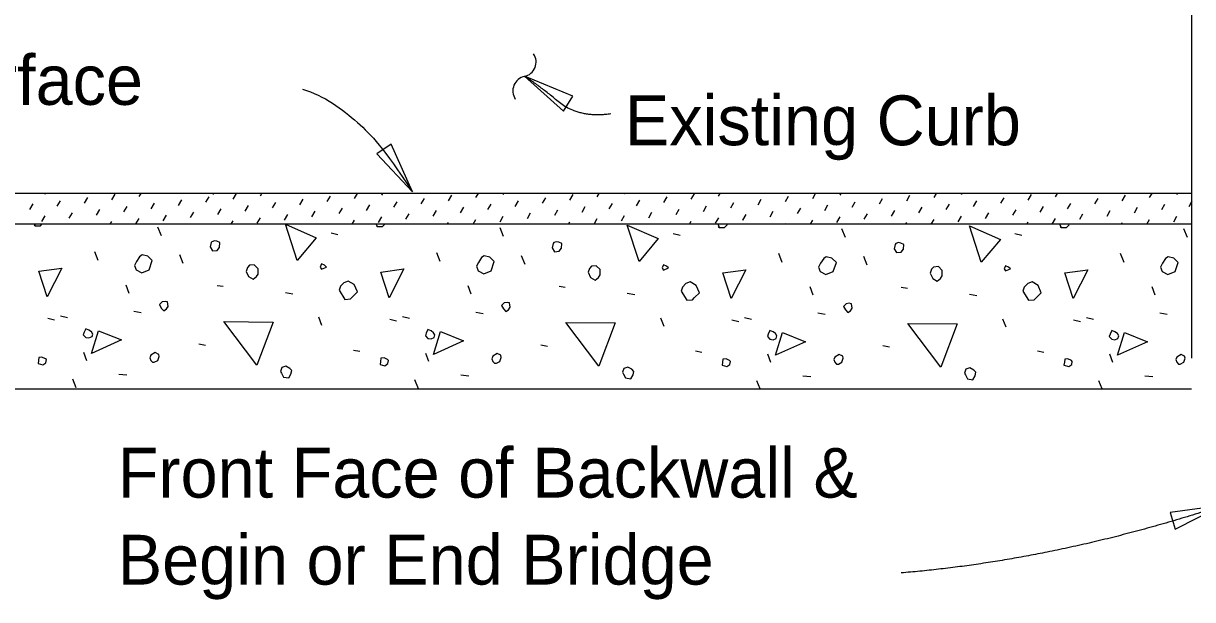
# Model space of a CAD drawing. Extents: x 21526.6 to 21598.7, y 56118.9 to 56155.9.
# Drawn here: x 21530.88 to 21535.614, y 56132.816 to 56135.148 of the extents above; entities that cross this region are included whole.
import ezdxf

# ---------------------------------------------------------------- set-up
doc = ezdxf.new("R2010")
doc.units = 0
for name, color, linetype in [('AdhocPoint_dp', 7, 'Continuous'), ('Border', 7, 'Continuous'), ('Patterning', 7, 'Continuous'), ('PlotBorder_dp', 7, 'Continuous')]:
    doc.layers.add(name, color=color, linetype=linetype)

msp = doc.modelspace()

# ---------------------------------------------------------------- linework, layer by layer
at = {"layer": 'AdhocPoint_dp'}
for p, q in [((21535.6096, 56135.2099), (21535.6096, 56133.7934)), ((21535.6096, 56134.46), (21527.2426, 56134.46)), ((21535.6096, 56134.335), (21527.2426, 56134.335)), ((21527.2426, 56133.6684), (21535.6096, 56133.6684))]:
    msp.add_line(p, q, dxfattribs=at)
at = {"layer": 'Patterning'}
for p, q in [((21530.9679, 56134.4567), (21530.9698, 56134.46)), ((21531.0168, 56134.4079), (21531.0297, 56134.4303)), ((21531.1274, 56134.4209), (21531.1404, 56134.4433)), ((21531.238, 56134.4338), (21531.251, 56134.4562)), ((21531.3487, 56134.4468), (21531.3563, 56134.46)), ((21531.4593, 56134.4598), (21531.4595, 56134.46)), ((21531.5081, 56134.4109), (21531.5211, 56134.4333)), ((21531.6188, 56134.4239), (21531.6317, 56134.4463)), ((21531.6499, 56134.4561), (21531.6501, 56134.4564)), ((21531.7294, 56134.4369), (21531.7424, 56134.4592)), ((21531.84, 56134.4498), (21531.846, 56134.46)), ((21531.9995, 56134.4139), (21532.0125, 56134.4363)), ((21532.1101, 56134.4269), (21532.1231, 56134.4493)), ((21532.2208, 56134.4399), (21532.2324, 56134.46)), ((21532.3314, 56134.4528), (21532.3356, 56134.46)), ((21532.4909, 56134.417), (21532.5038, 56134.4394)), ((21532.6015, 56134.4299), (21532.6145, 56134.4523)), ((21532.7121, 56134.4429), (21532.7221, 56134.46)), ((21532.8228, 56134.4559), (21532.8252, 56134.46)), ((21532.9822, 56134.42), (21532.9952, 56134.4424)), ((21533.0929, 56134.433), (21533.1058, 56134.4553)), ((21533.2035, 56134.4459), (21533.2117, 56134.46)), ((21533.3141, 56134.4589), (21533.3148, 56134.46)), ((21533.363, 56134.41), (21533.3759, 56134.4324)), ((21533.4736, 56134.423), (21533.4866, 56134.4454)), ((21533.5842, 56134.436), (21533.5972, 56134.4584)), ((21533.6949, 56134.4489), (21533.7013, 56134.46)), ((21533.8545, 56134.4139), (21533.8675, 56134.4363)), ((21533.9652, 56134.4269), (21533.9781, 56134.4493)), ((21534.0758, 56134.4399), (21534.0875, 56134.46)), ((21534.1864, 56134.4528), (21534.1906, 56134.46)), ((21534.3459, 56134.417), (21534.3589, 56134.4394)), ((21534.4565, 56134.4299), (21534.4695, 56134.4523)), ((21534.5672, 56134.4429), (21534.5771, 56134.46)), ((21534.6778, 56134.4559), (21534.6802, 56134.46)), ((21534.8373, 56134.42), (21534.8502, 56134.4424)), ((21534.9479, 56134.433), (21534.9609, 56134.4553)), ((21535.0585, 56134.4459), (21535.0667, 56134.46)), ((21535.2185, 56134.417), (21535.2315, 56134.4394)), ((21535.3292, 56134.4299), (21535.3421, 56134.4523)), ((21535.4398, 56134.4429), (21535.4497, 56134.46)), ((21535.5504, 56134.4559), (21535.5529, 56134.46)), ((21530.9061, 56134.3949), (21530.9191, 56134.4173)), ((21531.1762, 56134.372), (21531.1892, 56134.3944)), ((21531.2869, 56134.385), (21531.2998, 56134.4074)), ((21531.3975, 56134.398), (21531.4105, 56134.4204)), ((21531.557, 56134.3621), (21531.5699, 56134.3845)), ((21531.6676, 56134.3751), (21531.6806, 56134.3975)), ((21531.7782, 56134.388), (21531.7912, 56134.4104)), ((21531.8889, 56134.401), (21531.9018, 56134.4234)), ((21532.0483, 56134.3651), (21532.0613, 56134.3875)), ((21532.159, 56134.3781), (21532.1719, 56134.4005)), ((21532.2696, 56134.391), (21532.2826, 56134.4134)), ((21532.3802, 56134.404), (21532.3932, 56134.4264)), ((21532.5397, 56134.3681), (21532.5527, 56134.3905)), ((21532.6503, 56134.3811), (21532.6633, 56134.4035)), ((21532.761, 56134.3941), (21532.7739, 56134.4165)), ((21532.8716, 56134.407), (21532.8846, 56134.4294)), ((21533.0311, 56134.3712), (21533.044, 56134.3935)), ((21533.1417, 56134.3841), (21533.1547, 56134.4065)), ((21533.2523, 56134.3971), (21533.2653, 56134.4195)), ((21533.4118, 56134.3612), (21533.4248, 56134.3836)), ((21533.5224, 56134.3742), (21533.5354, 56134.3966)), ((21533.6331, 56134.3871), (21533.646, 56134.4095)), ((21533.7439, 56134.401), (21533.7569, 56134.4234)), ((21533.9034, 56134.3651), (21533.9163, 56134.3875)), ((21534.014, 56134.3781), (21534.027, 56134.4005)), ((21534.1246, 56134.391), (21534.1376, 56134.4134)), ((21534.2353, 56134.404), (21534.2482, 56134.4264)), ((21534.3947, 56134.3681), (21534.4077, 56134.3905)), ((21534.5054, 56134.3811), (21534.5183, 56134.4035)), ((21534.616, 56134.3941), (21534.629, 56134.4165)), ((21534.7266, 56134.407), (21534.7396, 56134.4294)), ((21534.8861, 56134.3712), (21534.8991, 56134.3935)), ((21534.9967, 56134.3841), (21535.0097, 56134.4065)), ((21535.1074, 56134.3971), (21535.1203, 56134.4195)), ((21535.2674, 56134.3681), (21535.2803, 56134.3905)), ((21535.378, 56134.3811), (21535.391, 56134.4035)), ((21535.4886, 56134.3941), (21535.5016, 56134.4165)), ((21535.5993, 56134.407), (21535.6122, 56134.4294)), ((21530.955, 56134.3461), (21530.9679, 56134.3685)), ((21531.0656, 56134.3591), (21531.0786, 56134.3815)), ((21531.2319, 56134.335), (21531.238, 56134.3456)), ((21531.3357, 56134.3362), (21531.3487, 56134.3586)), ((21531.4463, 56134.3491), (21531.4593, 56134.3715)), ((21531.6184, 56134.335), (21531.6188, 56134.3357)), ((21531.7215, 56134.335), (21531.7294, 56134.3486)), ((21531.8271, 56134.3392), (21531.84, 56134.3616)), ((21531.9377, 56134.3522), (21531.9507, 56134.3745)), ((21532.108, 56134.335), (21532.1101, 56134.3387)), ((21532.2112, 56134.335), (21532.2208, 56134.3516)), ((21532.3184, 56134.3422), (21532.3314, 56134.3646)), ((21532.4291, 56134.3552), (21532.442, 56134.3776)), ((21532.5977, 56134.335), (21532.6015, 56134.3417)), ((21532.7008, 56134.335), (21532.7121, 56134.3547)), ((21532.8098, 56134.3452), (21532.8228, 56134.3676)), ((21532.9204, 56134.3582), (21532.9334, 56134.3806)), ((21533.0873, 56134.335), (21533.0929, 56134.3447)), ((21533.1905, 56134.3353), (21533.2035, 56134.3577)), ((21533.3012, 56134.3482), (21533.3141, 56134.3706)), ((21533.5769, 56134.335), (21533.5842, 56134.3477)), ((21533.6821, 56134.3392), (21533.6951, 56134.3616)), ((21533.7925, 56134.3513), (21533.8055, 56134.3737)), ((21533.7927, 56134.3522), (21533.8057, 56134.3745)), ((21533.9631, 56134.335), (21533.9652, 56134.3387)), ((21534.0662, 56134.335), (21534.0758, 56134.3516)), ((21534.1735, 56134.3422), (21534.1864, 56134.3646)), ((21534.2841, 56134.3552), (21534.2971, 56134.3776)), ((21534.4527, 56134.335), (21534.4565, 56134.3417)), ((21534.5558, 56134.335), (21534.5672, 56134.3547)), ((21534.6648, 56134.3452), (21534.6778, 56134.3676)), ((21534.7755, 56134.3582), (21534.7884, 56134.3806)), ((21534.9423, 56134.335), (21534.9479, 56134.3447)), ((21535.0456, 56134.3353), (21535.0585, 56134.3577)), ((21535.1568, 56134.3552), (21535.1697, 56134.3776)), ((21535.3253, 56134.335), (21535.3292, 56134.3417)), ((21535.4285, 56134.335), (21535.4398, 56134.3547)), ((21535.5375, 56134.3452), (21535.5504, 56134.3676)), ((21531.4391, 56134.2884), (21531.425, 56134.3238)), ((21532.1255, 56134.3008), (21532.1538, 56134.2937)), ((21532.8238, 56134.2849), (21532.8097, 56134.3203)), ((21533.5102, 56134.2973), (21533.5385, 56134.2902)), ((21534.2085, 56134.2814), (21534.1943, 56134.3167)), ((21534.8945, 56134.2973), (21534.9228, 56134.2902)), ((21535.5928, 56134.2814), (21535.5786, 56134.3167)), ((21531.1828, 56134.1877), (21531.1687, 56134.223)), ((21531.5269, 56134.1759), (21531.5128, 56134.2113)), ((21532.5675, 56134.1841), (21532.5533, 56134.2195)), ((21532.9116, 56134.1724), (21532.8974, 56134.2077)), ((21533.9522, 56134.1806), (21533.938, 56134.216)), ((21534.2962, 56134.1689), (21534.2821, 56134.2042)), ((21535.3364, 56134.1806), (21535.3223, 56134.216)), ((21531.3083, 56134.0551), (21531.2959, 56134.0887)), ((21531.6648, 56134.0875), (21531.6895, 56134.084)), ((21531.9406, 56134.0593), (21531.9706, 56134.0539)), ((21532.693, 56134.0516), (21532.6806, 56134.0851)), ((21533.0495, 56134.084), (21533.0742, 56134.0805)), ((21533.3252, 56134.0557), (21533.3553, 56134.0504)), ((21534.0777, 56134.048), (21534.0653, 56134.0816)), ((21534.4341, 56134.0805), (21534.4589, 56134.0769)), ((21534.7099, 56134.0522), (21534.74, 56134.0469)), ((21535.462, 56134.048), (21535.4496, 56134.0816)), ((21531.0308, 56133.9649), (21531.0591, 56133.9579)), ((21531.3271, 56133.9832), (21531.3572, 56133.9779)), ((21532.089, 56133.9249), (21532.0767, 56133.9585)), ((21532.4155, 56133.9614), (21532.4437, 56133.9543)), ((21532.7118, 56133.9797), (21532.7419, 56133.9744)), ((21533.8001, 56133.9579), (21533.8284, 56133.9508)), ((21534.0965, 56133.9762), (21534.1265, 56133.9709)), ((21535.1844, 56133.9579), (21535.2127, 56133.9508)), ((21535.4808, 56133.9762), (21535.5108, 56133.9709)), ((21530.9784, 56133.955), (21531.0067, 56133.9479)), ((21532.363, 56133.9514), (21532.3913, 56133.9443)), ((21533.4737, 56133.9214), (21533.4613, 56133.955)), ((21533.7477, 56133.9479), (21533.776, 56133.9408)), ((21534.8584, 56133.9178), (21534.846, 56133.9514)), ((21535.132, 56133.9479), (21535.1603, 56133.9408)), ((21531.1368, 56133.7823), (21531.1245, 56133.8159)), ((21531.5905, 56133.8507), (21531.6171, 56133.8454)), ((21532.2163, 56133.8259), (21532.2428, 56133.8206)), ((21532.9752, 56133.8471), (21533.0017, 56133.8418)), ((21533.601, 56133.8224), (21533.6275, 56133.8171)), ((21534.3599, 56133.8436), (21534.3864, 56133.8383)), ((21534.9853, 56133.8224), (21535.0118, 56133.8171)), ((21532.5215, 56133.7788), (21532.5091, 56133.8124)), ((21533.9062, 56133.7753), (21533.8938, 56133.8089)), ((21535.2905, 56133.7753), (21535.2781, 56133.8089)), ((21531.267, 56133.7287), (21531.2989, 56133.7251)), ((21532.6517, 56133.7251), (21532.6835, 56133.7216)), ((21534.0364, 56133.7216), (21534.0682, 56133.7181)), ((21535.4207, 56133.7216), (21535.4525, 56133.7181)), ((21531.0944, 56133.6727), (21531.0803, 56133.7081)), ((21532.4791, 56133.6692), (21532.465, 56133.7046)), ((21533.8627, 56133.6684), (21533.8496, 56133.701)), ((21535.247, 56133.6684), (21535.2339, 56133.701))]:
    msp.add_line(p, q, dxfattribs=at)
for points in [[(21530.9257, 56134.335), (21530.9282, 56134.3291), (21530.9247, 56134.3326)], [(21530.9282, 56134.3291), (21530.9495, 56134.3291), (21530.9554, 56134.335)], [(21531.9883, 56134.1883), (21531.9406, 56134.335), (21532.0661, 56134.2802), (21531.9883, 56134.1883)], [(21532.3089, 56134.335), (21532.3129, 56134.3256), (21532.3094, 56134.3291)], [(21532.3129, 56134.3256), (21532.3341, 56134.3256), (21532.3436, 56134.335)], [(21533.373, 56134.1848), (21533.3252, 56134.3315), (21533.4507, 56134.2767), (21533.373, 56134.1848)], [(21533.6927, 56134.335), (21533.6923, 56134.3344), (21533.6976, 56134.322), (21533.6941, 56134.3256)], [(21533.6976, 56134.322), (21533.7188, 56134.322), (21533.7294, 56134.3326), (21533.7288, 56134.335)], [(21534.7576, 56134.1812), (21534.7099, 56134.328), (21534.8354, 56134.2731), (21534.7576, 56134.1812)], [(21535.077, 56134.335), (21535.0766, 56134.3344), (21535.0819, 56134.322), (21535.0784, 56134.3256)], [(21535.0819, 56134.322), (21535.1031, 56134.322), (21535.1137, 56134.3326), (21535.1131, 56134.335)], [(21531.6365, 56134.2431), (21531.6453, 56134.2272), (21531.6648, 56134.229), (21531.6736, 56134.2413), (21531.6754, 56134.2608), (21531.663, 56134.2661), (21531.6542, 56134.2678), (21531.6436, 56134.2643), (21531.64, 56134.2608), (21531.6365, 56134.2431)], [(21533.0212, 56134.2396), (21533.03, 56134.2237), (21533.0495, 56134.2254), (21533.0583, 56134.2378), (21533.0601, 56134.2572), (21533.0477, 56134.2625), (21533.0389, 56134.2643), (21533.0282, 56134.2608), (21533.0247, 56134.2572), (21533.0212, 56134.2396)], [(21534.4059, 56134.236), (21534.4147, 56134.2201), (21534.4341, 56134.2219), (21534.443, 56134.2343), (21534.4447, 56134.2537), (21534.4324, 56134.259), (21534.4235, 56134.2608), (21534.4129, 56134.2572), (21534.4094, 56134.2537), (21534.4059, 56134.236)], [(21531.3366, 56134.1505), (21531.3596, 56134.1382), (21531.3896, 56134.1505), (21531.402, 56134.1877), (21531.3843, 56134.2053), (21531.3614, 56134.2107), (21531.3507, 56134.2036), (21531.3384, 56134.1841), (21531.3295, 56134.1682), (21531.3366, 56134.1505)], [(21532.7213, 56134.147), (21532.7443, 56134.1346), (21532.7743, 56134.147), (21532.7867, 56134.1841), (21532.769, 56134.2018), (21532.746, 56134.2071), (21532.7354, 56134.2), (21532.723, 56134.1806), (21532.7142, 56134.1647), (21532.7213, 56134.147)], [(21534.106, 56134.1435), (21534.1289, 56134.1311), (21534.159, 56134.1435), (21534.1714, 56134.1806), (21534.1537, 56134.1983), (21534.1307, 56134.2036), (21534.1201, 56134.1965), (21534.1077, 56134.1771), (21534.0989, 56134.1612), (21534.106, 56134.1435)], [(21535.4902, 56134.1435), (21535.5132, 56134.1311), (21535.5433, 56134.1435), (21535.5557, 56134.1806), (21535.538, 56134.1983), (21535.515, 56134.2036), (21535.5044, 56134.1965), (21535.492, 56134.1771), (21535.4832, 56134.1612), (21535.4902, 56134.1435)], [(21530.976, 56134.0409), (21530.9424, 56134.1452), (21531.0361, 56134.1576), (21530.976, 56134.0409)], [(21531.7815, 56134.1441), (21531.7921, 56134.1229), (21531.8097, 56134.1123), (21531.8239, 56134.1229), (21531.831, 56134.1335), (21531.831, 56134.1547), (21531.815, 56134.1706), (21531.7956, 56134.1689), (21531.7868, 56134.16), (21531.7815, 56134.1441)], [(21532.0873, 56134.1529), (21532.1067, 56134.1618), (21532.0997, 56134.1689), (21532.0873, 56134.1742), (21532.082, 56134.1618), (21532.0873, 56134.1529)], [(21532.3607, 56134.0374), (21532.3271, 56134.1417), (21532.4208, 56134.1541), (21532.3607, 56134.0374)], [(21533.1661, 56134.1406), (21533.1767, 56134.1194), (21533.1944, 56134.1087), (21533.2086, 56134.1194), (21533.2156, 56134.13), (21533.2156, 56134.1512), (21533.1997, 56134.1671), (21533.1803, 56134.1653), (21533.1714, 56134.1565), (21533.1661, 56134.1406)], [(21533.472, 56134.1494), (21533.4914, 56134.1582), (21533.4843, 56134.1653), (21533.472, 56134.1706), (21533.4667, 56134.1582), (21533.472, 56134.1494)], [(21533.7453, 56134.0339), (21533.7117, 56134.1382), (21533.8054, 56134.1505), (21533.7453, 56134.0339)], [(21534.5508, 56134.137), (21534.5614, 56134.1158), (21534.5791, 56134.1052), (21534.5932, 56134.1158), (21534.6003, 56134.1264), (21534.6003, 56134.1476), (21534.5844, 56134.1635), (21534.5649, 56134.1618), (21534.5561, 56134.1529), (21534.5508, 56134.137)], [(21534.8566, 56134.1459), (21534.8761, 56134.1547), (21534.869, 56134.1618), (21534.8566, 56134.1671), (21534.8513, 56134.1547), (21534.8566, 56134.1459)], [(21535.1296, 56134.0339), (21535.096, 56134.1382), (21535.1897, 56134.1505), (21535.1296, 56134.0339)], [(21532.158, 56134.0681), (21532.181, 56134.031), (21532.2039, 56134.0327), (21532.2128, 56134.0416), (21532.2322, 56134.061), (21532.2199, 56134.0911), (21532.1951, 56134.1052), (21532.1774, 56134.0981), (21532.1633, 56134.084), (21532.158, 56134.0681)], [(21533.5427, 56134.0646), (21533.5656, 56134.0274), (21533.5886, 56134.0292), (21533.5975, 56134.038), (21533.6169, 56134.0575), (21533.6045, 56134.0875), (21533.5798, 56134.1017), (21533.5621, 56134.0946), (21533.548, 56134.0805), (21533.5427, 56134.0646)], [(21534.927, 56134.0646), (21534.9499, 56134.0274), (21534.9729, 56134.0292), (21534.9818, 56134.038), (21535.0012, 56134.0575), (21534.9888, 56134.0875), (21534.9641, 56134.1017), (21534.9464, 56134.0946), (21534.9323, 56134.0805), (21534.927, 56134.0646)], [(21531.4385, 56133.9956), (21531.4491, 56133.985), (21531.4597, 56133.9921), (21531.4668, 56134.0027), (21531.4633, 56134.0204), (21531.4544, 56134.0221), (21531.442, 56134.0204), (21531.4314, 56134.0098), (21531.4385, 56133.9956)], [(21532.8232, 56133.9921), (21532.8338, 56133.9815), (21532.8444, 56133.9885), (21532.8515, 56133.9991), (21532.8479, 56134.0168), (21532.8391, 56134.0186), (21532.8267, 56134.0168), (21532.8161, 56134.0062), (21532.8232, 56133.9921)], [(21534.2079, 56133.9885), (21534.2185, 56133.9779), (21534.2291, 56133.985), (21534.2361, 56133.9956), (21534.2326, 56134.0133), (21534.2238, 56134.0151), (21534.2114, 56134.0133), (21534.2008, 56134.0027), (21534.2079, 56133.9885)], [(21531.1333, 56133.8765), (21531.1457, 56133.8748), (21531.1581, 56133.8801), (21531.1616, 56133.8907), (21531.1563, 56133.8995), (21531.1457, 56133.9066), (21531.1333, 56133.9119), (21531.1262, 56133.8978), (21531.1227, 56133.8872), (21531.1333, 56133.8765)], [(21531.8256, 56133.764), (21531.6913, 56133.9408), (21531.8911, 56133.939), (21531.8256, 56133.764)], [(21533.2103, 56133.7605), (21533.076, 56133.9373), (21533.2757, 56133.9355), (21533.2103, 56133.7605)], [(21534.595, 56133.757), (21534.4607, 56133.9337), (21534.6604, 56133.932), (21534.595, 56133.757)], [(21531.1557, 56133.8118), (21531.1839, 56133.9037), (21531.2776, 56133.8666), (21531.1557, 56133.8118)], [(21532.518, 56133.873), (21532.5304, 56133.8712), (21532.5427, 56133.8765), (21532.5463, 56133.8872), (21532.541, 56133.896), (21532.5304, 56133.9031), (21532.518, 56133.9084), (21532.5109, 56133.8942), (21532.5074, 56133.8836), (21532.518, 56133.873)], [(21532.5403, 56133.8082), (21532.5686, 56133.9002), (21532.6623, 56133.863), (21532.5403, 56133.8082)], [(21533.9027, 56133.8695), (21533.915, 56133.8677), (21533.9274, 56133.873), (21533.9309, 56133.8836), (21533.9256, 56133.8925), (21533.915, 56133.8995), (21533.9027, 56133.9048), (21533.8956, 56133.8907), (21533.8921, 56133.8801), (21533.9027, 56133.8695)], [(21533.925, 56133.8047), (21533.9533, 56133.8966), (21534.047, 56133.8595), (21533.925, 56133.8047)], [(21535.2869, 56133.8695), (21535.2993, 56133.8677), (21535.3117, 56133.873), (21535.3152, 56133.8836), (21535.3099, 56133.8925), (21535.2993, 56133.8995), (21535.2869, 56133.9048), (21535.2799, 56133.8907), (21535.2763, 56133.8801), (21535.2869, 56133.8695)], [(21535.3093, 56133.8047), (21535.3376, 56133.8966), (21535.4313, 56133.8595), (21535.3093, 56133.8047)], [(21531.4032, 56133.7764), (21531.4102, 56133.7764), (21531.4244, 56133.7835), (21531.4297, 56133.7994), (21531.4279, 56133.8082), (21531.4138, 56133.8153), (21531.3961, 56133.8047), (21531.3925, 56133.7941), (21531.3961, 56133.7835), (21531.4032, 56133.7764)], [(21530.9395, 56133.7711), (21530.9589, 56133.7658), (21530.9713, 56133.7746), (21530.9731, 56133.787), (21530.9695, 56133.7905), (21530.9554, 56133.7976), (21530.943, 56133.7959), (21530.9412, 56133.7835), (21530.9395, 56133.7711)], [(21532.3242, 56133.7676), (21532.3436, 56133.7623), (21532.356, 56133.7711), (21532.3577, 56133.7835), (21532.3542, 56133.787), (21532.3401, 56133.7941), (21532.3277, 56133.7923), (21532.3259, 56133.7799), (21532.3242, 56133.7676)], [(21532.7878, 56133.7729), (21532.7949, 56133.7729), (21532.809, 56133.7799), (21532.8143, 56133.7959), (21532.8126, 56133.8047), (21532.7984, 56133.8118), (21532.7808, 56133.8012), (21532.7772, 56133.7905), (21532.7808, 56133.7799), (21532.7878, 56133.7729)], [(21533.7088, 56133.764), (21533.7283, 56133.7587), (21533.7407, 56133.7676), (21533.7424, 56133.7799), (21533.7389, 56133.7835), (21533.7247, 56133.7905), (21533.7124, 56133.7888), (21533.7106, 56133.7764), (21533.7088, 56133.764)], [(21534.1725, 56133.7693), (21534.1796, 56133.7693), (21534.1937, 56133.7764), (21534.199, 56133.7923), (21534.1973, 56133.8012), (21534.1831, 56133.8082), (21534.1654, 56133.7976), (21534.1619, 56133.787), (21534.1654, 56133.7764), (21534.1725, 56133.7693)], [(21535.0931, 56133.764), (21535.1126, 56133.7587), (21535.1249, 56133.7676), (21535.1267, 56133.7799), (21535.1232, 56133.7835), (21535.109, 56133.7905), (21535.0967, 56133.7888), (21535.0949, 56133.7764), (21535.0931, 56133.764)], [(21535.5568, 56133.7693), (21535.5639, 56133.7693), (21535.578, 56133.7764), (21535.5833, 56133.7923), (21535.5815, 56133.8012), (21535.5674, 56133.8082), (21535.5497, 56133.7976), (21535.5462, 56133.787), (21535.5497, 56133.7764), (21535.5568, 56133.7693)], [(21531.9246, 56133.7322), (21531.9335, 56133.7163), (21531.9547, 56133.7128), (21531.9635, 56133.7287), (21531.9671, 56133.7428), (21531.9582, 56133.7517), (21531.9423, 56133.7605), (21531.9264, 56133.7552), (21531.9211, 56133.7393), (21531.9246, 56133.7322)], [(21533.3093, 56133.7287), (21533.3182, 56133.7128), (21533.3394, 56133.7092), (21533.3482, 56133.7251), (21533.3517, 56133.7393), (21533.3429, 56133.7481), (21533.327, 56133.757), (21533.3111, 56133.7517), (21533.3058, 56133.7357), (21533.3093, 56133.7287)], [(21534.694, 56133.7251), (21534.7028, 56133.7092), (21534.724, 56133.7057), (21534.7329, 56133.7216), (21534.7364, 56133.7357), (21534.7276, 56133.7446), (21534.7117, 56133.7534), (21534.6958, 56133.7481), (21534.6905, 56133.7322), (21534.694, 56133.7251)]]:
    msp.add_lwpolyline(points, dxfattribs=at)
at = {"layer": 'PlotBorder_dp'}
for points in [[(21532.9092, 56134.934), (21533.0667, 56134.7933), (21533.1043, 56134.8531)], [(21532.4557, 56134.4666), (21532.3692, 56134.6593), (21532.3106, 56134.6201)], [(21535.7321, 56133.1961), (21535.5227, 56133.1687), (21535.5434, 56133.1013)]]:
    msp.add_lwpolyline(points, close=True, dxfattribs=at)
for centre, start, end in [((21532.8964, 56134.9917), 282.0365, 33.7637), ((21532.9213, 56134.8751), 102.0365, 213.7637)]:
    msp.add_arc(centre, 0.0596, start, end, dxfattribs=at)
for points, degree in [([(21533.2579, 56134.7814), (21533.1271, 56134.7638), (21532.9641, 56134.8995), (21532.9092, 56134.934)], 2), ([(21532.01, 56134.8816), (21532.0975, 56134.8568), (21532.248, 56134.7428), (21532.335, 56134.647), (21532.4557, 56134.4666)], 3), ([(21535.7321, 56133.1961), (21535.0684, 56132.9765), (21534.4337, 56132.9235)], 2)]:
    msp.add_open_spline(points, degree=degree, dxfattribs=at)

# ---------------------------------------------------------------- texts
at = {"layer": 'Border'}
for s, p in [('Final Riding Surface', (21528.9369, 56134.8183)), ('Existing Curb', (21533.3155, 56134.6548))]:
    msp.add_text(s, height=0.2016, dxfattribs=at).set_placement(p)
at = {"layer": 'PlotBorder_dp'}
for s, p in [('Front Face of Backwall &', (21531.262, 56133.2284)), ('Begin or End Bridge', (21531.262, 56132.8764))]:
    msp.add_text(s, height=0.2016, dxfattribs=at).set_placement(p)

doc.saveas('drawing.dxf')
